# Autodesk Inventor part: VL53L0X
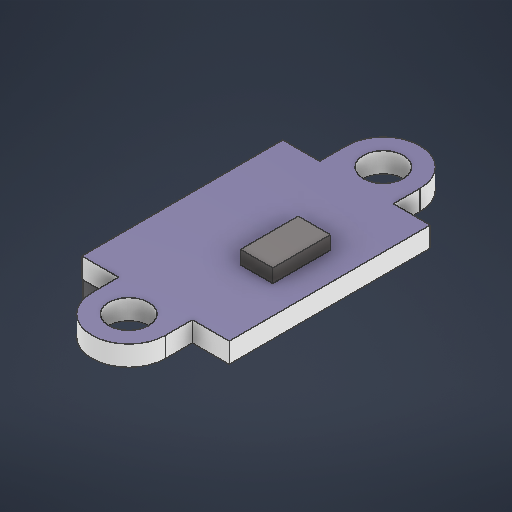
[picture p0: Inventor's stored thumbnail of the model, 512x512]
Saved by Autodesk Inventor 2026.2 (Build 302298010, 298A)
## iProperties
Created: 2026-04
Part Number: VL53L0X
Material: PPS 플라스틱
Document SubType Name: Modeling
Designer: work
Density: 1.637 g/cm^3
Appearance: 매끄러움 - 흰색
Author: work
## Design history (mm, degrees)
sketch "스케치1"
  geometry: L1 (-5.5, 7.5)-(5.5, 7.5); L2 (5.5, 7.5)-(5.5, -7.5); L3 (5.5, -7.5)-(-5.5, -7.5); L4 (-5.5, -7.5)-(-5.5, 7.5); L5 (-5.5, 7.5)-(5.5, -7.5); L6 (5.5, 7.5)-(-5.5, -7.5); L7 (0, 9.5)-(0, -9.5); L8 (0, 9.5)-(0, -9.5); L9 (-2.75, 9.5)-(-2.75, -9.5); L10 (2.75, -9.5)-(2.75, 9.5); C1 r 1.5 at (0, 9.5); C2 r 1.5 at (0, -9.5); A1 r 2.75 centre (0, 9.5) between (2.75, 9.5) and (-2.75, 9.5); A2 r 2.75 centre (0, -9.5) between (-2.75, -9.5) and (2.75, -9.5); 6 further points
  constraints: 22 end point, 6 midpoint, 4 centre point, 4 equal length, 4 point on circle, 4 tangent, 2 coincident, 1 horizontal, 1 perpendicular, 1 vertical
  dimensions: "d0" = 11 distance of L2.end L3.end; "d1" = 15 distance of L1.end L2.end; "d2" = 19 distance of L7.start L7.end; "d3" = 5.5 diameter of A2; "d4" = 3 diameter of C1; "d5" = 3 diameter of C2
extrude "돌출1" new body sketch "스케치1" distance "d6" = 1.5; taper "d7" = 0 deg
sketch "스케치2"
  geometry: L1 (5.5, -7.5)-(5.5, 7.5) reference; L2 (5.5, 0)-(-5.5, 0); L3 (-5.5, 7.5)-(-5.5, -7.5) reference; L4 (3.4, -2.15)-(1, -2.15); L5 (1, -2.15)-(1, 2.15); L6 (1, 2.15)-(3.4, 2.15); L7 (3.4, 2.15)-(3.4, -2.15); L8 (3.4, -2.15)-(1, 2.15); L9 (1, -2.15)-(3.4, 2.15); 2 further points
  constraints: 14 end point, 4 midpoint, 2 parallel, 1 horizontal, 1 perpendicular, 1 point on line
  dimensions: "d8" = 2.4 distance of L5.end L6.end; "d9" = 4.3 distance of L4.end L5.end; "d10" = 4.5 distance between parallel lines of L1 L5
extrude "돌출2" join sketch "스케치2" distance "d11" = 1; taper "d12" = 0 deg
sketch "스케치3"
  geometry: L1 (0, 0)-(-5.5, 0); L2 (-5.5, -7.5)-(-5.5, 7.5) reference; L3 (-3.1, 7.45)-(-5.5, 7.45); L4 (-5.5, 7.45)-(-5.5, -7.45); L5 (-5.5, -7.45)-(-3.1, -7.45); L6 (-3.1, -7.45)-(-3.1, 7.45); L7 (-3.1, 7.45)-(-5.5, -7.45); L8 (-5.5, 7.45)-(-3.1, -7.45); L9 (-5.45, -7.45)-(-5.45, 7.45); 2 further points
  constraints: 16 end point, 4 point on line, 3 midpoint, 2 parallel, 2 perpendicular, 1 horizontal
  dimensions: "d13" = 2.4 distance of L4.end L5.end; "d14" = 14.9 distance of L5.end L3.start; "d17" = 0.05 distance between parallel lines of L2 L9
extrude "돌출3" join sketch "스케치3" distance "d15" = 1.5; taper "d16" = 0 deg
node "솔리드1"
